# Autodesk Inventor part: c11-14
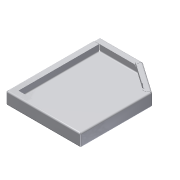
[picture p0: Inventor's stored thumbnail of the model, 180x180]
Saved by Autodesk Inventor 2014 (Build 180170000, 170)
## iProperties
Created: 2011-01
Part Number: c11-14
Material: Steel, Mild
Document SubType Name: Sheet Metal
Designer: Thom Tremblay
Density: 7.86 g/cm^3
Sheet Metal Rule: Steel - 16ga
Flat Pattern Width: 34.6788 cm
Flat Pattern Length: 40.6788 cm
Flat Pattern Area: 1410.69 cm^2
Sheet Metal Width: 346.788 mm
Sheet Metal Length: 406.788 mm
Sheet Metal Area: 141069.500 mm^2
Appearance: Ceramic
Author: Thom Tremblay
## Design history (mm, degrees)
node "Face1"
  sketch "Sketch1"
    geometry: L1 (0, 0)-(240, 0); L2 (240, 0)-(240, 300); L3 (240, 300)-(0, 300); L4 (0, 300)-(0, 0); L5 (140, 300)-(240, 229.979)
    constraints: 10 end point, 2 parallel, 2 point on line, 1 horizontal, 1 perpendicular
    dimensions: "d0" = 240 distance of L3.end L2.end; "d1" = 300 distance of L2.end L1.end; "d2" = 35 deg angle of L3 L5; "d3" = 100 distance from line of L2 L5.start
node "Flange1"
node "Flange2"
node "Flange3"
body "Solid1"
face "Plate1" dims "Thickness" = 1.524 (derived)
sketch "Sketch2"
  geometry: L1 through (-150, 0) direction (1, 0); L2 through (0, 20) direction (0, 1); L3 (0, 40)-(-300, 40); L4 (-300, 40)-(-300, 0)
  constraints: 6 end point, 1 horizontal, 1 perpendicular, 1 vertical
face "Plate2" dims "d5" = 1.524 (= BendReliefWidth), "d6" = 0.762 (= BendReliefDepth), "d7" = 3.048 (= MinimumRemnant), "d8" = 3.048 (= BendRadius), "d9" = 40, "d10" = 90 deg, "d11" = 3.048 (= BendRadius), "d12" = 6.096 (= CornerReliefSize), "d13" = 0.762 (= GapSize), "d14" = 3.048 (= JacobiRadiusSize), "SeamGap" = 0.01, "Thickness" = 1.524 (derived)
bend "Bend1" dims "d5" = 1.524 (= BendReliefWidth), "d6" = 0.762 (= BendReliefDepth), "d7" = 3.048 (= MinimumRemnant), "d8" = 3.048 (= BendRadius), "d9" = 40, "d10" = 90 deg, "d11" = 3.048 (= BendRadius), "SeamGap" = 0.01, "Thickness" = 1.524 (derived)
feature "Corner1" dims "d9" = 40, "d10" = 90 deg, "d12" = 6.096 (= CornerReliefSize), "d13" = 0.762 (= GapSize), "d14" = 3.048 (= JacobiRadiusSize)
sketch "Sketch3"
  geometry: L1 through (-117.937, 0) direction (1, 1.89e-49); L2 through (0, 10) direction (-3.49e-49, 1); L3 (0, 20)-(-235.874, 20); L4 (-235.874, 20)-(-235.874, 0)
  constraints: 6 end point, 1 horizontal, 1 perpendicular, 1 vertical
face "Plate3" dims "d15" = 1.524 (= BendReliefWidth), "d16" = 0.762 (= BendReliefDepth), "d17" = 3.048 (= MinimumRemnant), "d18" = 3.048 (= BendRadius), "d19" = 20, "d20" = 90 deg, "d21" = 3.048 (= BendRadius), "d22" = 6.096 (= CornerReliefSize), "d23" = 0.762 (= GapSize), "d24" = 3.048 (= JacobiRadiusSize), "d26" = 10, "SeamGap" = 0.01, "Thickness" = 1.524 (derived)
bend "Bend2" dims "d15" = 1.524 (= BendReliefWidth), "d16" = 0.762 (= BendReliefDepth), "d17" = 3.048 (= MinimumRemnant), "d18" = 3.048 (= BendRadius), "d19" = 20, "d20" = 90 deg, "d21" = 3.048 (= BendRadius), "SeamGap" = 0.01, "Thickness" = 1.524 (derived)
feature "Corner2" dims "d19" = 20, "d20" = 90 deg, "d22" = 6.096 (= CornerReliefSize), "d23" = 0.762 (= GapSize), "d24" = 3.048 (= JacobiRadiusSize)
sketch "Sketch4"
  geometry: L1 (-94.531, 0)-(-10, 0); L2 (-10, 0)-(-10, 15); L3 (-10, 15)-(-94.531, 15); L4 (-94.531, 15)-(-94.531, 0)
  constraints: 8 end point
face "Plate4" dims "d27" = 1.524 (= BendReliefWidth), "d28" = 0.762 (= BendReliefDepth), "d29" = 3.048 (= MinimumRemnant), "d30" = 3.048 (= BendRadius), "d31" = 10, "d32" = 10, "d33" = 15, "d34" = 90 deg, "d35" = 3.048 (= BendRadius), "d36" = 6.096 (= CornerReliefSize), "d37" = 0.762 (= GapSize), "d38" = 3.048 (= JacobiRadiusSize), "SeamGap" = 0.01, "Thickness" = 1.524 (derived)
bend "Bend3" dims "d27" = 1.524 (= BendReliefWidth), "d28" = 0.762 (= BendReliefDepth), "d29" = 3.048 (= MinimumRemnant), "d30" = 3.048 (= BendRadius), "d33" = 15, "d34" = 90 deg, "d35" = 3.048 (= BendRadius), "SeamGap" = 0.01, "Thickness" = 1.524 (derived)
feature "Corner3" dims "d33" = 15, "d34" = 90 deg, "d36" = 6.096 (= CornerReliefSize), "d37" = 0.762 (= GapSize), "d38" = 3.048 (= JacobiRadiusSize)
feature "Definition1"
fillet "Fillet1" dims "d0" = 5
fillet "Fillet2" dims "d1" = 5
fillet "Fillet3" dims "d2" = 5
fillet "Fillet4" dims "d3" = 2
fillet "Fillet5" dims "d4" = 2
other parameters: "BendRadius" = 3.048 (= 2 x Thickness), "BendReliefWidth" = 1.524 (= Thickness), "BendReliefDepth" = 0.762 (= 0.5 x Thickness), "CornerReliefSize" = 6.096 (= 4 x Thickness), "MinimumRemnant" = 3.048 (= 2 x Thickness), "TransitionRadius" = 3.048 (= BendRadius), "JacobiRadiusSize" = 3.048 (= BendRadius), "GapSize" = 0.762 (= 0.5 x Thickness), "d4" = 3.048 (= BendRadius), "BendRadius" = 3.048, "BendReliefDepth" = 0.762, "BendReliefWidth" = 1.524, "CornerReliefSize" = 6.096, "GapSize" = 0.762, "JacobiRadiusSize" = 3.048, "MinimumRemnant" = 3.048, "Thickness" = 1.524, "TransitionRadius" = 3.048
